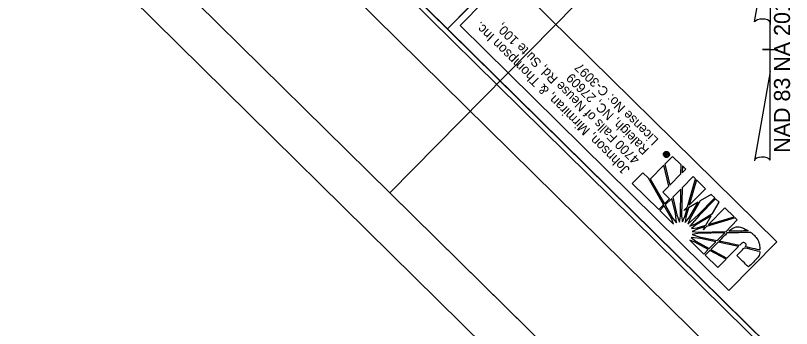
# Model space of a CAD drawing. Extents: x 1266642 to 1268668, y 770349 to 772370.
# Drawn here: x 1266642 to 1267053.3, y 771294.7 to 771460.5 of the extents above; entities that cross this region are included whole.
import ezdxf

# ---------------------------------------------------------------- set-up
doc = ezdxf.new("R2010")
doc.units = 0
for name, color, linetype in [('COGO Default Chain', 7, 'Continuous'), ('Exist Roads EOT', 7, 'Continuous'), ('Exist Utilities Power Pole CELL', 7, 'Continuous'), ('Prop Conc 1ft 6in Curb and Gutter', 7, 'Continuous'), ('Prop Conc 4in Sidewalk', 7, 'Continuous'), ('Prop EOT', 7, 'Continuous'), ('Prop Horizontal Alignment Station Label', 7, 'Continuous'), ('Prop Plan Preparation Crest', 7, 'Continuous'), ('Prop Plan Preparation Watershed Post Construction', 7, 'Continuous'), ('Typical Terminator CELL', 7, 'Continuous')]:
    doc.layers.add(name, color=color, linetype=linetype)

msp = doc.modelspace()

# ---------------------------------------------------------------- linework, layer by layer
at = {"layer": 'COGO Default Chain'}
for p, q in [((1266985.89, 771385.8), (1266986.1, 771386.01)), ((1266986.1, 771386.01), (1266985.89, 771385.8)), ((1266990.28, 771385.91), (1266986.21, 771381.77)), ((1266986.48, 771386.4), (1266986.42, 771386.46)), ((1266986.48, 771386.4), (1266986.67, 771386.59)), ((1266986.67, 771386.59), (1266986.48, 771386.4)), ((1266986.9, 771385.99), (1266986.48, 771386.4)), ((1266986.64, 771386.62), (1266986.67, 771386.59)), ((1266986.67, 771386.59), (1266986.86, 771386.41)), ((1266986.86, 771386.41), (1266987.09, 771386.65)), ((1266987.9, 771387.01), (1266986.9, 771385.99)), ((1266986.91, 771386.84), (1266986.9, 771386.85)), ((1266986.91, 771386.84), (1266987.09, 771387.02)), ((1266987.09, 771387.02), (1266986.91, 771386.84)), ((1266987.09, 771386.65), (1266986.91, 771386.84)), ((1266987.08, 771387.03), (1266987.09, 771387.02)), ((1266987.09, 771387.02), (1266987.28, 771386.84)), ((1266987.28, 771386.84), (1266987.67, 771387.24)), ((1266987.67, 771387.24), (1266987.9, 771387.01)), ((1266987.88, 771387.82), (1266987.87, 771387.83)), ((1266987.88, 771387.82), (1266988.09, 771388.04)), ((1266988.09, 771388.04), (1266987.88, 771387.82)), ((1266988.09, 771388.05), (1266988.09, 771388.04)), ((1266994.8, 771381.46), (1266990.28, 771385.91)), ((1266986.21, 771381.77), (1266988.84, 771370.62)), ((1266985.7, 771381.25), (1266978.45, 771373.88)), ((1266988.3, 771370.07), (1266985.7, 771381.25)), ((1266994.71, 771376.59), (1266994.8, 771381.46)), ((1266995.47, 771380.81), (1266995.35, 771377.24)), ((1266995.35, 771377.24), (1266997.19, 771379.11)), ((1266997.19, 771379.11), (1266995.47, 771380.81)), ((1266974.51, 771377.26), (1266968.86, 771371.51)), ((1266977.5, 771374.32), (1266974.51, 771377.26)), ((1266985.5, 771360.37), (1266977.5, 771374.32)), ((1266978.45, 771373.88), (1266985.89, 771360.76)), ((1266988.84, 771370.62), (1266994.71, 771376.59)), ((1267001.18, 771375.19), (1266995.29, 771369.2)), ((1266998.18, 771359.12), (1267002.36, 771374.03)), ((1267002.36, 771374.03), (1267001.18, 771375.19)), ((1266968.86, 771371.51), (1266982.89, 771357.71)), ((1266985.15, 771366.86), (1266988.3, 771370.07)), ((1267002.88, 771373.46), (1266999.12, 771360.08)), ((1267007.66, 771368.75), (1267002.88, 771373.46)), ((1266988.58, 771363.49), (1266985.15, 771366.86)), ((1266994.61, 771368.5), (1266990.4, 771364.23)), ((1266994.39, 771354.22), (1266994.61, 771368.5)), ((1266995.29, 771369.2), (1266995.01, 771354.26)), ((1266999.12, 771360.08), (1267007.66, 771368.75)), ((1267010.75, 771365.71), (1267004.84, 771362.27)), ((1267012.6, 771363.89), (1267010.75, 771365.71)), ((1266985.93, 771360.81), (1266988.58, 771363.49)), ((1266989.82, 771363.63), (1266986.3, 771360.14)), ((1266991.72, 771355.7), (1266989.82, 771363.63)), ((1266990.4, 771364.23), (1266992.56, 771354.94)), ((1267003.75, 771361.61), (1266998.7, 771358.61)), ((1266998.85, 771353.17), (1267003.75, 771361.61)), ((1267004.84, 771362.27), (1266999.55, 771353.07)), ((1267003.85, 771354.99), (1267012.6, 771363.89)), ((1267013.08, 771363.43), (1267004.33, 771354.53)), ((1267011.43, 771355.58), (1267014.91, 771361.63)), ((1267014.91, 771361.63), (1267013.08, 771363.43)), ((1266982.89, 771357.71), (1266985.42, 771360.29)), ((1266985.8, 771359.64), (1266983.44, 771357.24)), ((1266983.44, 771357.24), (1266990.81, 771349.92)), ((1266985.42, 771360.29), (1266985.5, 771360.37)), ((1266989.8, 771352.65), (1266985.8, 771359.64)), ((1266985.89, 771360.76), (1266985.93, 771360.81)), ((1266986.3, 771360.14), (1266990.47, 771352.95)), ((1266996.26, 771357.17), (1266998.18, 771359.12)), ((1266997.91, 771358.15), (1266996.26, 771357.17)), ((1266996.73, 771354.09), (1266997.91, 771358.15)), ((1266998.7, 771358.61), (1266997.35, 771353.78)), ((1267017.96, 771358.69), (1267009.25, 771349.75)), ((1267022.93, 771353.8), (1267017.96, 771358.69)), ((1266990.47, 771352.95), (1266992.27, 771350.66)), ((1266992.27, 771350.66), (1266991.72, 771355.7)), ((1266992.56, 771354.94), (1266993.87, 771351.12)), ((1266993.87, 771351.12), (1266994.39, 771354.22)), ((1266995.01, 771354.26), (1266995.44, 771351.15)), ((1266995.44, 771351.15), (1266996.73, 771354.09)), ((1266997.35, 771353.78), (1266996.97, 771350.82)), ((1266996.97, 771350.82), (1266998.85, 771353.17)), ((1266998.33, 771350.06), (1267003.85, 771354.99)), ((1266999.55, 771353.07), (1266998.33, 771350.06)), ((1267004.33, 771354.53), (1266999.43, 771348.98)), ((1267002.45, 771350.22), (1267011.43, 771355.58)), ((1267010.74, 771354.44), (1267002.46, 771349.47)), ((1267007.86, 771349.38), (1267010.74, 771354.44)), ((1267023.45, 771353.29), (1267008.31, 771348.79)), ((1267009.25, 771349.75), (1267022.93, 771353.8)), ((1267024.55, 771352.2), (1267023.45, 771353.29)), ((1266990.81, 771349.92), (1266989.8, 771352.65)), ((1266999.43, 771348.98), (1267002.45, 771350.22)), ((1267002.46, 771349.47), (1267000.24, 771347.6)), ((1267003.23, 771348), (1267007.86, 771349.38)), ((1267008.31, 771348.79), (1267006.57, 771347.03)), ((1267018.6, 771346.15), (1267024.55, 771352.2)), ((1267000.24, 771347.6), (1267003.23, 771348)), ((1267003.66, 771345.04), (1267000.6, 771344.5)), ((1267003.53, 771347.4), (1267000.62, 771346.06)), ((1267000.62, 771346.06), (1267003.73, 771345.68)), ((1267007.43, 771348.57), (1267003.53, 771347.4)), ((1267017.9, 771345.44), (1267003.66, 771345.04)), ((1267003.73, 771345.68), (1267018.6, 771346.15)), ((1267006.57, 771347.03), (1267007.43, 771348.57)), ((1267013.81, 771341.28), (1267017.9, 771345.44)), ((1267002.06, 771340.52), (1266999.31, 771341.56)), ((1266999.31, 771341.56), (1267006.82, 771334.17)), ((1267005.1, 771342.45), (1267000.13, 771342.92)), ((1267000.13, 771342.92), (1267002.57, 771341.04)), ((1267000.6, 771344.5), (1267004.41, 771343.29)), ((1267002.57, 771341.04), (1267009.68, 771337.08)), ((1267004.41, 771343.29), (1267013.81, 771341.28)), ((1267013.23, 771340.69), (1267005.1, 771342.45)), ((1267009.68, 771337.08), (1267013.23, 771340.69)), ((1267009.17, 771336.56), (1267002.06, 771340.52)), ((1267006.82, 771334.17), (1267009.17, 771336.56)), ((1267014.36, 771340.45), (1267010.56, 771336.59)), ((1267010.56, 771336.59), (1267019.08, 771331.9)), ((1267025.2, 771338.12), (1267014.36, 771340.45)), ((1267019.08, 771331.9), (1267025.2, 771338.12)), ((1267010.08, 771336.1), (1267007.55, 771333.52)), ((1267007.55, 771333.52), (1267014.22, 771326.96)), ((1267018.58, 771331.39), (1267010.08, 771336.1)), ((1267014.22, 771326.96), (1267018.58, 771331.39))]:
    msp.add_line(p, q, dxfattribs=at)
msp.add_lwpolyline([(1267045.47, 771340.63), (1266902.98, 771481.03), (1266877.64, 771455.32), (1267020.13, 771314.92)], close=True, dxfattribs=at)
for points in [[(1266988.84, 771370.62), (1266994.71, 771376.59), (1266994.8, 771381.46), (1266990.28, 771385.91), (1266986.21, 771381.77), (1266988.84, 771370.62), (1266988.84, 771370.62)], [(1266986.8, 771387.62), (1266986.86, 771387.67), (1266986.88, 771387.72), (1266986.92, 771387.76), (1266987, 771387.89), (1266987.21, 771387.68)], [(1266985.89, 771360.76), (1266985.93, 771360.81), (1266988.58, 771363.49), (1266985.15, 771366.86), (1266988.3, 771370.07), (1266985.7, 771381.25), (1266978.45, 771373.88), (1266985.89, 771360.76)], [(1266997.19, 771379.11), (1266997.19, 771379.11), (1266995.47, 771380.81), (1266995.35, 771377.24), (1266997.19, 771379.11)], [(1266968.86, 771371.51), (1266982.89, 771357.71), (1266985.42, 771360.29), (1266985.5, 771360.37), (1266977.5, 771374.32), (1266974.51, 771377.26), (1266968.86, 771371.51)], [(1266995.44, 771351.15), (1266996.73, 771354.09), (1266997.91, 771358.15), (1266996.26, 771357.17), (1266998.18, 771359.12), (1267002.36, 771374.03), (1267001.18, 771375.19), (1266995.29, 771369.2), (1266995.01, 771354.26), (1266995.44, 771351.15)], [(1267007.66, 771368.75), (1267002.88, 771373.46), (1266999.12, 771360.08), (1267007.66, 771368.75)], [(1266993.87, 771351.12), (1266994.39, 771354.22), (1266994.61, 771368.5), (1266990.4, 771364.23), (1266992.56, 771354.94), (1266993.87, 771351.12)], [(1266998.33, 771350.06), (1267003.85, 771354.99), (1267012.6, 771363.89), (1267010.75, 771365.71), (1267004.84, 771362.27), (1266999.55, 771353.07), (1266998.33, 771350.06)], [(1266992.27, 771350.66), (1266991.72, 771355.7), (1266989.82, 771363.63), (1266986.3, 771360.14), (1266990.47, 771352.95), (1266992.27, 771350.66)], [(1266996.97, 771350.82), (1266998.85, 771353.17), (1267003.75, 771361.61), (1266998.7, 771358.61), (1266997.35, 771353.78), (1266996.97, 771350.82)], [(1267002.45, 771350.22), (1267011.43, 771355.58), (1267014.91, 771361.63), (1267013.08, 771363.43), (1267004.33, 771354.53), (1266999.43, 771348.98), (1267002.45, 771350.22)], [(1266989.8, 771352.65), (1266985.8, 771359.64), (1266983.44, 771357.24), (1266990.81, 771349.92), (1266989.8, 771352.65)], [(1267022.93, 771353.8), (1267017.96, 771358.69), (1267009.25, 771349.75), (1267022.93, 771353.8)], [(1267000.24, 771347.6), (1267003.23, 771348), (1267007.86, 771349.38), (1267010.74, 771354.44), (1267002.46, 771349.47), (1267000.24, 771347.6)], [(1267000.62, 771346.06), (1267003.73, 771345.68), (1267018.6, 771346.15), (1267024.55, 771352.2), (1267023.45, 771353.29), (1267008.31, 771348.79), (1267006.57, 771347.03), (1267007.43, 771348.57), (1267003.53, 771347.4), (1267000.62, 771346.06)], [(1267013.81, 771341.28), (1267017.9, 771345.44), (1267003.66, 771345.04), (1267000.6, 771344.5), (1267004.41, 771343.29), (1267013.81, 771341.28)], [(1267002.06, 771340.52), (1266999.31, 771341.56), (1267006.82, 771334.17), (1267009.17, 771336.56), (1267002.06, 771340.52)], [(1267009.68, 771337.08), (1267013.23, 771340.69), (1267005.1, 771342.45), (1267000.13, 771342.92), (1267002.57, 771341.04), (1267009.68, 771337.08)], [(1267025.2, 771338.12), (1267014.36, 771340.45), (1267010.56, 771336.59), (1267019.08, 771331.9), (1267025.2, 771338.12)], [(1267018.58, 771331.39), (1267010.08, 771336.1), (1267007.55, 771333.52), (1267014.22, 771326.96), (1267018.58, 771331.39)]]:
    msp.add_lwpolyline(points, dxfattribs=at)
for points, degree in [([(1266985.89, 771385.8), (1266985.57, 771386.11), (1266985.41, 771386.48), (1266985.4, 771386.92), (1266985.38, 771387.34), (1266985.53, 771387.72), (1266985.84, 771388.03)], 3), ([(1266987.87, 771387.83), (1266987.62, 771388.07), (1266987.32, 771388.2), (1266986.97, 771388.2), (1266986.62, 771388.2), (1266986.31, 771388.06), (1266986.06, 771387.81), (1266985.82, 771387.56), (1266985.69, 771387.25), (1266985.69, 771386.9), (1266985.71, 771386.56), (1266985.84, 771386.27), (1266986.1, 771386.01)], 3), ([(1266985.84, 771388.03), (1266986.15, 771388.35), (1266986.53, 771388.51), (1266986.96, 771388.52), (1266987.39, 771388.51), (1266987.77, 771388.36), (1266988.09, 771388.05)], 3), ([(1266988.09, 771388.04), (1266988.4, 771387.74), (1266988.56, 771387.37), (1266988.56, 771386.92), (1266988.58, 771386.49), (1266988.42, 771386.11), (1266988.11, 771385.8), (1266987.8, 771385.48), (1266987.43, 771385.32), (1266987, 771385.34), (1266986.57, 771385.34), (1266986.2, 771385.49), (1266985.89, 771385.8)], 3), ([(1266986.1, 771386.01), (1266986.35, 771385.76), (1266986.64, 771385.64), (1266986.98, 771385.63), (1266987.33, 771385.63), (1266987.64, 771385.77), (1266987.89, 771386.02), (1266988.14, 771386.27), (1266988.26, 771386.58), (1266988.26, 771386.93), (1266988.26, 771387.28), (1266988.13, 771387.57), (1266987.88, 771387.82)], 3), ([(1266986.42, 771386.46), (1266986.16, 771386.72), (1266986.13, 771386.95), (1266986.33, 771387.15), (1266986.42, 771387.25), (1266986.53, 771387.28), (1266986.67, 771387.26)], 3), ([(1266986.9, 771386.85), (1266986.75, 771386.99), (1266986.63, 771387.02), (1266986.55, 771386.93), (1266986.48, 771386.86), (1266986.5, 771386.76), (1266986.64, 771386.62)], 3), ([(1266986.67, 771387.26), (1266986.64, 771387.36), (1266986.68, 771387.48), (1266986.8, 771387.62)], 2), ([(1266987.21, 771387.68), (1266987.19, 771387.6), (1266987.15, 771387.53), (1266987.08, 771387.45), (1266986.99, 771387.36), (1266986.94, 771387.3), (1266986.94, 771387.24)], 3), ([(1266986.94, 771387.24), (1266986.95, 771387.2), (1266986.99, 771387.12), (1266987.08, 771387.03)], 2), ([(1267020.02, 771346.2), (1267020.02, 771346.2), (1267030.49, 771346.45), (1267030.49, 771346.45), (1267027.33, 771348.33), (1267023.14, 771349.13), (1267020.02, 771346.2)], 3), ([(1267028.81, 771339.87), (1267029.2, 771339.48), (1267029.33, 771338.93), (1267028.75, 771338.05), (1267028.75, 771338.05), (1267036.45, 771336.3), (1267036.45, 771336.3), (1267036.5, 771339.3), (1267035.06, 771342.55), (1267033.06, 771344.51), (1267032.54, 771345.02), (1267032.1, 771345.36), (1267031.45, 771345.79), (1267031.45, 771345.79), (1267019.32, 771345.5), (1267019.32, 771345.5), (1267019.32, 771345.5), (1267014.9, 771341), (1267014.9, 771341), (1267014.9, 771341), (1267025.75, 771338.68), (1267025.75, 771338.68), (1267027.41, 771340.36), (1267028.26, 771340.42), (1267028.81, 771339.87)], 3), ([(1267028.81, 771339.87), (1267029.2, 771339.48), (1267029.33, 771338.93), (1267028.75, 771338.05), (1267028.75, 771338.05), (1267036.45, 771336.3), (1267036.45, 771336.3), (1267036.5, 771339.3), (1267035.06, 771342.55), (1267033.06, 771344.51), (1267032.54, 771345.02), (1267032.1, 771345.36), (1267031.45, 771345.79), (1267031.45, 771345.79), (1267019.32, 771345.5), (1267019.32, 771345.5), (1267019.32, 771345.5), (1267014.9, 771341), (1267014.9, 771341), (1267014.9, 771341), (1267025.75, 771338.68), (1267025.75, 771338.68), (1267027.41, 771340.36), (1267028.26, 771340.42), (1267028.81, 771339.87)], 3), ([(1267024.3, 771333.37), (1267024.3, 771333.37), (1267030.47, 771327.29), (1267030.47, 771327.29), (1267030.47, 771327.29), (1267034.28, 771331.16), (1267034.28, 771331.16), (1267034.28, 771331.16), (1267034.68, 771331.57), (1267034.68, 771331.57), (1267035.87, 771332.78), (1267036.41, 771334.13), (1267036.5, 771335.62), (1267036.5, 771335.62), (1267028.39, 771337.53), (1267028.31, 771337.46), (1267028.31, 771337.46), (1267024.3, 771333.37), (1267024.3, 771333.37)], 3)]:
    msp.add_open_spline(points, degree=degree, dxfattribs=at)
at = {"layer": 'Exist Roads EOT'}
for p, q in [((1267033.72, 771457.21), (1267041.92, 771503.56)), ((1267041.97, 771503.56), (1267041.97, 771455.76)), ((1267041.97, 771430.96), (1267041.97, 771457.16)), ((1267041.97, 771455.76), (1267041.97, 771457.11)), ((1267037.97, 771442.56), (1267037.92, 771442.56)), ((1267041.52, 771442.56), (1267037.97, 771442.56)), ((1267038.02, 771442.56), (1267046.02, 771442.56)), ((1267041.97, 771430.96), (1267033.62, 771383.71)), ((1267042.02, 771383.91), (1267041.97, 771430.96))]:
    msp.add_line(p, q, dxfattribs=at)
for centre, start_param, end_param in [((1267037.86, 771456.71), 0.216388, 2.908219), ((1267037.86, 771383.54), 0.201328, 3.141593)]:
    msp.add_ellipse(centre, major_axis=(4.23, -0.03), ratio=0.461098, start_param=start_param, end_param=end_param, dxfattribs=at)
at = {"layer": 'Exist Utilities Power Pole CELL'}
msp.add_lwpolyline([(1267796.95, 770541.08), (1268533.89, 771289.02), (1267501.02, 772306.72), (1266885.88, 771682.41), (1266992.76, 771577.1), (1266870.95, 771453.46)], close=True, dxfattribs=at)
at = {"layer": 'Prop Conc 1ft 6in Curb and Gutter'}
for points in [[(1266728.44, 771593.89), (1267796.95, 770541.08), (1268533.89, 771289.02), (1267465.41, 772341.81)], [(1266870.95, 771453.46), (1266728.44, 771593.89), (1266746.05, 771611.71), (1266888.56, 771471.33)]]:
    msp.add_lwpolyline(points, close=True, dxfattribs=at)
at = {"layer": 'Prop Conc 4in Sidewalk'}
msp.add_line((1266642.03, 771530.38), (1267841.21, 770348.8), dxfattribs=at)
at = {"layer": 'Prop EOT'}
msp.add_lwpolyline([(1268644.99, 771183.08), (1267458.27, 772352.36), (1266717.81, 771600.88), (1267904.53, 770431.59)], close=True, dxfattribs=at)
at = {"layer": 'Prop Horizontal Alignment Station Label'}
msp.add_lwpolyline([(1268668.29, 771188.2), (1267469.1, 772369.78), (1266700.57, 771589.79), (1267899.75, 770408.22)], close=True, dxfattribs=at)
at = {"layer": 'Prop Plan Preparation Crest'}
for points in [[(1267738.44, 770481.67), (1268475.35, 771229.61), (1267406.88, 772282.39), (1266818.36, 771685.1), (1266988.78, 771517.18), (1266840.35, 771366.54)], [(1266988.78, 771517.18), (1266818.34, 771685.12), (1266669.89, 771534.49), (1266840.35, 771366.54)]]:
    msp.add_lwpolyline(points, close=True, dxfattribs=at)
at = {"layer": 'Prop Plan Preparation Watershed Post Construction'}
msp.add_lwpolyline([(1268439.74, 771264.7), (1267442.48, 772247.31), (1266853.97, 771650.02), (1266988.78, 771517.18), (1266840.35, 771366.54), (1267702.79, 770516.76)], close=True, dxfattribs=at)
at = {"layer": 'Typical Terminator CELL'}
msp.add_lwpolyline([(1268439.74, 771264.7), (1267442.48, 772247.31), (1266853.97, 771650.02), (1266988.78, 771517.18), (1266840.35, 771366.54), (1267702.79, 770516.76)], close=True, dxfattribs=at)

# ---------------------------------------------------------------- texts
at = {"layer": 'COGO Default Chain'}
for s, height, p in [('Johnson, Mirmiran, & Thompson Inc.', 5.1112, (1266967.94, 771379.32)), ('4700 Falls of Neuse Rd, Suite 100, ', 4.9652, (1266973.21, 771384.67)), ('License No: C-3097', 4.9652, (1266983.16, 771394.77)), ('Raleigh, NC, 27609', 4.9652, (1266978.18, 771389.72))]:
    msp.add_text(s, height=height, rotation=135.4239, dxfattribs=at).set_placement(p)
at = {"layer": 'Exist Roads EOT'}
msp.add_text('NAD 83 NA 2011', height=8.5, rotation=90, dxfattribs=at).set_placement((1267052.49, 771387.82))

doc.saveas('drawing.dxf')
